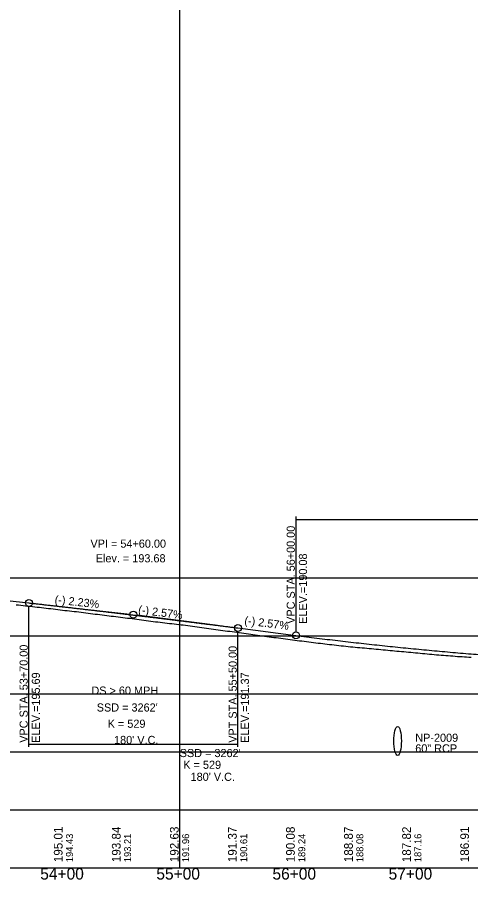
# Model space of a CAD drawing. Extents: x 69 to 2003113, y 512 to 837401.
# Drawn here: x 1892738 to 1893128, y 821790 to 822533 of the extents above; entities that cross this region are included whole.
import ezdxf

# ---------------------------------------------------------------- set-up
doc = ezdxf.new("R2010")
doc.units = 0
for name, color, linetype in [('BR_AUTO DIMENSION', 7, 'Continuous'), ('BR_BORDER LINES', 7, 'Continuous'), ('BR_CENTER LINE BASELINE', 7, 'Continuous'), ('BR_CONCRETE', 7, 'Continuous'), ('BR_GRID DOTS', 7, 'Continuous'), ('BR_GRID LINES', 7, 'Continuous'), ('BR_TEXT', 7, 'Continuous'), ('RD_HC_Points', 7, 'Continuous'), ('RD_SHT_ID', 7, 'Continuous'), ('RD_SHT_IplotShp', 7, 'Continuous'), ('RD_XS_PaveShd', 7, 'Continuous')]:
    doc.layers.add(name, color=color, linetype=linetype)

msp = doc.modelspace()

# ---------------------------------------------------------------- linework, layer by layer
at = {"layer": 'BR_AUTO DIMENSION'}
for p, q in [((1892877.53, 821800.13), (1892877.53, 823276.64)), ((1891422.53, 822050.13), (1894248.3, 822050.13)), ((1891422.53, 822000.13), (1894248.3, 822000.13)), ((1891422.53, 821950.13), (1894248.3, 821950.13)), ((1891422.53, 821900.13), (1894248.3, 821900.13)), ((1891422.53, 821850.13), (1894248.3, 821850.13)), ((1891422.53, 821800.13), (1894248.3, 821800.13))]:
    msp.add_line(p, q, dxfattribs=at)
at = {"layer": 'BR_BORDER LINES'}
msp.add_line((1891422.53, 821800.13), (1893922.53, 821800.13), dxfattribs=at)
at = {"layer": 'BR_CENTER LINE BASELINE'}
for p, q in [((1892766.97, 822026.39), (1892834.55, 822018.86)), ((1892907.95, 822009.48), (1892840.51, 822018.14))]:
    msp.add_line(p, q, dxfattribs=at)
msp.add_circle((1892837.53, 822018.53), 3, dxfattribs=at)
at = {"layer": 'BR_GRID DOTS'}
for p, q in [((1892977.53, 822103.03), (1892977.53, 822003.53)), ((1892977.53, 822100.53), (1893427.53, 822100.53)), ((1892747.53, 821904.46), (1892747.53, 822025.56)), ((1892927.53, 821904.46), (1892927.53, 822003.96)), ((1892747.53, 821906.96), (1892927.53, 821906.96))]:
    msp.add_line(p, q, dxfattribs=at)
for centre in [(1892747.53, 822028.56), (1892927.53, 822006.96), (1892977.53, 822000.53)]:
    msp.add_circle(centre, 3, dxfattribs=at)
at = {"layer": 'BR_GRID LINES'}
for p, q in [((1892592.53, 822045.84), (1892747.53, 822028.56)), ((1892927.53, 822006.96), (1892977.53, 822000.53))]:
    msp.add_line(p, q, dxfattribs=at)
for points in [[(1892747.53, 822028.56), (1892751.13, 822028.16), (1892754.73, 822027.75), (1892758.33, 822027.35), (1892761.93, 822026.94), (1892765.53, 822026.54), (1892769.13, 822026.13), (1892772.73, 822025.72), (1892776.33, 822025.31), (1892779.93, 822024.9), (1892783.53, 822024.48), (1892787.13, 822024.07), (1892790.73, 822023.65), (1892794.33, 822023.24), (1892797.93, 822022.82), (1892801.53, 822022.4), (1892805.13, 822021.98), (1892808.73, 822021.56), (1892812.33, 822021.14), (1892815.93, 822020.71), (1892819.53, 822020.29), (1892823.13, 822019.86), (1892826.73, 822019.43), (1892830.33, 822019), (1892833.93, 822018.57), (1892837.53, 822018.14), (1892841.13, 822017.71), (1892844.73, 822017.28), (1892848.33, 822016.84), (1892851.93, 822016.4), (1892855.53, 822015.97), (1892859.13, 822015.53), (1892862.73, 822015.09), (1892866.33, 822014.65), (1892869.93, 822014.21), (1892873.53, 822013.76), (1892877.13, 822013.32), (1892880.73, 822012.87), (1892884.33, 822012.42), (1892887.93, 822011.97), (1892891.53, 822011.53), (1892895.13, 822011.07), (1892898.73, 822010.62), (1892902.33, 822010.17), (1892905.93, 822009.71), (1892909.53, 822009.26), (1892913.13, 822008.8), (1892916.73, 822008.34), (1892920.33, 822007.88), (1892923.93, 822007.42), (1892927.53, 822006.96)], [(1892977.53, 822000.53), (1892986.53, 821999.39), (1892995.53, 821998.27), (1893004.53, 821997.18), (1893013.53, 821996.11), (1893022.53, 821995.06), (1893031.53, 821994.04), (1893040.53, 821993.04), (1893049.53, 821992.07), (1893058.53, 821991.12), (1893067.53, 821990.2), (1893076.53, 821989.3), (1893085.53, 821988.43), (1893094.53, 821987.58), (1893103.53, 821986.76), (1893112.53, 821985.96), (1893121.53, 821985.19), (1893130.53, 821984.44), (1893139.53, 821983.71), (1893148.53, 821983.01), (1893157.53, 821982.33), (1893166.53, 821981.68), (1893175.53, 821981.06), (1893184.53, 821980.46), (1893193.53, 821979.88), (1893202.53, 821979.33), (1893211.53, 821978.8), (1893220.53, 821978.29), (1893229.53, 821977.82), (1893238.53, 821977.36), (1893247.53, 821976.93), (1893256.53, 821976.53), (1893265.53, 821976.15), (1893274.53, 821975.79), (1893283.53, 821975.46), (1893292.53, 821975.16), (1893301.53, 821974.87), (1893310.53, 821974.62), (1893319.53, 821974.39), (1893328.53, 821974.18), (1893337.53, 821973.99), (1893346.53, 821973.84), (1893355.53, 821973.7), (1893364.53, 821973.59), (1893373.53, 821973.51), (1893382.53, 821973.45), (1893391.53, 821973.42), (1893400.53, 821973.41), (1893409.53, 821973.42), (1893418.53, 821973.46), (1893427.53, 821973.52)]]:
    msp.add_spline(points, degree=3, dxfattribs=at)
at = {"layer": 'BR_TEXT'}
for points in [[(1892736.53, 822027.01), (1892738.53, 822026.79), (1892740.53, 822026.56), (1892742.53, 822026.34), (1892744.53, 822026.11), (1892746.53, 822025.89), (1892748.53, 822025.67), (1892750.53, 822025.45), (1892752.53, 822025.24), (1892754.53, 822025.02), (1892756.53, 822024.8), (1892758.53, 822024.56), (1892760.53, 822024.33), (1892762.53, 822024.09), (1892764.53, 822023.86), (1892766.53, 822023.62), (1892768.53, 822023.37), (1892770.53, 822023.13), (1892772.53, 822022.88), (1892774.53, 822022.64), (1892776.53, 822022.39), (1892778.53, 822022.14), (1892780.53, 822021.92), (1892782.53, 822021.7), (1892784.53, 822021.47), (1892786.53, 822021.25), (1892788.53, 822021.03), (1892790.53, 822020.78), (1892792.53, 822020.52), (1892794.53, 822020.27), (1892796.53, 822020.01), (1892798.53, 822019.76), (1892800.53, 822019.5), (1892802.53, 822019.25), (1892804.53, 822019), (1892806.53, 822018.75), (1892808.53, 822018.5), (1892810.53, 822018.25), (1892812.53, 822018), (1892814.53, 822017.76), (1892816.53, 822017.52), (1892818.53, 822017.28), (1892820.53, 822017.04), (1892822.53, 822016.79)], [(1892822.53, 822016.79), (1892824.53, 822016.55), (1892826.53, 822016.3), (1892828.53, 822016.05), (1892830.53, 822015.8), (1892832.53, 822015.55), (1892834.53, 822015.3), (1892836.53, 822015.04), (1892838.53, 822014.79), (1892840.53, 822014.53), (1892842.53, 822014.28), (1892844.53, 822014.01), (1892846.53, 822013.74), (1892848.53, 822013.46), (1892850.53, 822013.19), (1892852.53, 822012.92), (1892854.53, 822012.66), (1892856.53, 822012.4), (1892858.53, 822012.15), (1892860.53, 822011.89), (1892862.53, 822011.64), (1892864.53, 822011.4), (1892866.53, 822011.19), (1892868.53, 822010.97), (1892870.53, 822010.76), (1892872.53, 822010.55), (1892874.53, 822010.34), (1892876.53, 822010.08), (1892878.53, 822009.81), (1892880.53, 822009.55), (1892882.53, 822009.28), (1892884.53, 822009.01), (1892886.53, 822008.73), (1892888.53, 822008.45), (1892890.53, 822008.17), (1892892.53, 822007.89), (1892894.53, 822007.62), (1892896.53, 822007.35), (1892898.53, 822007.08), (1892900.53, 822006.81), (1892902.53, 822006.53), (1892904.53, 822006.26), (1892906.53, 822005.99), (1892908.53, 822005.72), (1892910.53, 822005.44), (1892912.53, 822005.17), (1892914.53, 822004.9), (1892916.53, 822004.62), (1892918.53, 822004.36), (1892920.53, 822004.1), (1892922.53, 822003.84), (1892924.53, 822003.58), (1892926.53, 822003.32), (1892928.53, 822003.04), (1892930.53, 822002.73), (1892932.53, 822002.43), (1892934.53, 822002.12), (1892936.53, 822001.82), (1892938.53, 822001.51), (1892940.53, 822001.23), (1892942.53, 822000.95), (1892944.53, 822000.67), (1892946.53, 822000.39), (1892948.53, 822000.11), (1892950.53, 821999.83), (1892952.53, 821999.59), (1892954.53, 821999.36), (1892956.53, 821999.12), (1892958.53, 821998.89), (1892960.53, 821998.65), (1892962.53, 821998.4), (1892964.53, 821998.1), (1892966.53, 821997.81), (1892968.53, 821997.52), (1892970.53, 821997.23), (1892972.53, 821996.94), (1892974.53, 821996.65), (1892976.53, 821996.42), (1892978.53, 821996.19), (1892980.53, 821995.97), (1892982.53, 821995.75), (1892984.53, 821995.52), (1892986.53, 821995.27), (1892988.53, 821995.02), (1892990.53, 821994.77), (1892992.53, 821994.52), (1892994.53, 821994.27), (1892996.53, 821994.02), (1892998.53, 821993.79), (1893000.53, 821993.55), (1893002.53, 821993.32), (1893004.53, 821993.08), (1893006.53, 821992.84), (1893008.53, 821992.6), (1893010.53, 821992.36), (1893012.53, 821992.12), (1893014.53, 821991.88), (1893016.53, 821991.67), (1893018.53, 821991.46), (1893020.53, 821991.25), (1893022.53, 821991.05)], [(1893022.53, 821991.05), (1893024.53, 821990.84), (1893026.53, 821990.63), (1893028.53, 821990.46), (1893030.53, 821990.28), (1893032.53, 821990.11), (1893034.53, 821989.93), (1893036.53, 821989.75), (1893038.53, 821989.57), (1893040.53, 821989.39), (1893042.53, 821989.22), (1893044.53, 821989.04), (1893046.53, 821988.84), (1893048.53, 821988.64), (1893050.53, 821988.44), (1893052.53, 821988.24), (1893054.53, 821988.04), (1893056.53, 821987.85), (1893058.53, 821987.66), (1893060.53, 821987.47), (1893062.53, 821987.28), (1893064.53, 821987.09), (1893066.53, 821986.91), (1893068.53, 821986.73), (1893070.53, 821986.56), (1893072.53, 821986.38), (1893074.53, 821986.21), (1893076.53, 821986.03), (1893078.53, 821985.85), (1893080.53, 821985.66), (1893082.53, 821985.46), (1893084.53, 821985.26), (1893086.53, 821985.06), (1893088.53, 821984.86), (1893090.53, 821984.66), (1893092.53, 821984.46), (1893094.53, 821984.26), (1893096.53, 821984.1), (1893098.53, 821983.94), (1893100.53, 821983.78), (1893102.53, 821983.62), (1893104.53, 821983.46), (1893106.53, 821983.3), (1893108.53, 821983.14), (1893110.53, 821982.98), (1893112.53, 821982.83), (1893114.53, 821982.67), (1893116.53, 821982.51), (1893118.53, 821982.38), (1893120.53, 821982.25), (1893122.53, 821982.12), (1893124.53, 821982), (1893126.53, 821981.85), (1893128.53, 821981.69)]]:
    msp.add_lwpolyline(points, dxfattribs=at)
at = {"layer": 'RD_XS_PaveShd'}
msp.add_ellipse((1893065.04, 821909.59), major_axis=(0, 12.47), ratio=0.261899, dxfattribs=at)

# ---------------------------------------------------------------- texts
at = {"layer": 'BR_CENTER LINE BASELINE'}
for s, rotation, p in [('(-) 2.23%', 353.63822, (1892769.46, 822028.13)), ('(-) 2.57%', 352.67757, (1892841.35, 822019.4)), ('(-) 2.57%', 352.67757, (1892932.81, 822010.17))]:
    msp.add_text(s, height=7, rotation=rotation, dxfattribs=at).set_placement(p)
at = {"layer": 'BR_CONCRETE'}
for s, height, p in [('VPC STA. 56+00.00 ', 7, (1892976.53, 822010.53)), ('ELEV.=190.08', 7, (1892987.03, 822010.53)), ('VPC STA. 53+70.00 ', 7, (1892746.53, 821908.05)), ('VPT STA. 55+50.00 ', 7, (1892926.53, 821908.05)), ('ELEV.=195.69', 7, (1892757.03, 821908.05)), ('ELEV.=191.37', 7, (1892937.03, 821908.05)), ('194.43', 6, (1892785.53, 821805.13)), ('193.21', 6, (1892835.53, 821805.13)), ('191.96', 6, (1892885.53, 821805.13)), ('190.61', 6, (1892935.53, 821805.13)), ('189.24', 6, (1892985.53, 821805.13)), ('188.08', 6, (1893035.53, 821805.13)), ('187.16', 6, (1893085.53, 821805.13))]:
    msp.add_text(s, height=height, rotation=90, dxfattribs=at).set_placement(p)
at = {"layer": 'BR_GRID DOTS'}
for s, p in [('DS > 60 MPH', (1892801.37, 821949.5)), ("SSD = 3262'", (1892805.97, 821934.96)), ('K = 529', (1892815.39, 821920.96)), ("180' V.C.", (1892820.89, 821906.96)), ("SSD = 3262'", (1892877.41, 821895.69)), ('K = 529', (1892880.52, 821885.59)), ("180' V.C.", (1892886.79, 821875.23))]:
    msp.add_text(s, height=7, dxfattribs=at).set_placement(p)
at = {"layer": 'RD_HC_Points'}
for s, p in [('195.01', (1892776.53, 821805.13)), ('193.84', (1892826.53, 821805.13)), ('192.63', (1892876.53, 821805.13)), ('191.37', (1892926.53, 821805.13)), ('190.08', (1892976.53, 821805.13)), ('188.87', (1893026.53, 821805.13)), ('187.82', (1893076.53, 821805.13)), ('186.91', (1893126.53, 821805.13))]:
    msp.add_text(s, height=7.5, rotation=90, dxfattribs=at).set_placement(p)
at = {"layer": 'RD_SHT_ID'}
for s, p in [('54+00', (1892757.29, 821790.13)), ('55+00', (1892857.29, 821790.13)), ('56+00', (1892957.29, 821790.13)), ('57+00', (1893057.29, 821790.13))]:
    msp.add_text(s, height=10, dxfattribs=at).set_placement(p)
at = {"layer": 'RD_SHT_IplotShp'}
for s, p in [('VPI = 54+60.00', (1892800.55, 822076.15)), ('Elev. = 193.68', (1892805.1, 822063.53))]:
    msp.add_text(s, height=7, dxfattribs=at).set_placement(p)
at = {"layer": 'RD_XS_PaveShd'}
for s, p in [('NP-2009', (1893080.26, 821908.86)), ('60" RCP', (1893080.26, 821899.68))]:
    msp.add_text(s, height=7, dxfattribs=at).set_placement(p)

doc.saveas('drawing.dxf')
